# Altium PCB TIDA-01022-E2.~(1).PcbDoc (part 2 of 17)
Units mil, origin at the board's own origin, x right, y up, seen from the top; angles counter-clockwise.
Board outline 6929.13 x 11614.17 mil, 12 copper layers (L1_Top Layer, L2_GND, L3_GND, L4_Signal Layer 1, L5_GND, L6_PWR, L7_GND/PWR, L8_PWR, L9_GND/PWR, L10_Signal Layer 2, L11_GND, L12_Bottom Layer), stack 64.6 mil thick; 1711 components, 1001 nets, 5985 pads, 3200 vias.
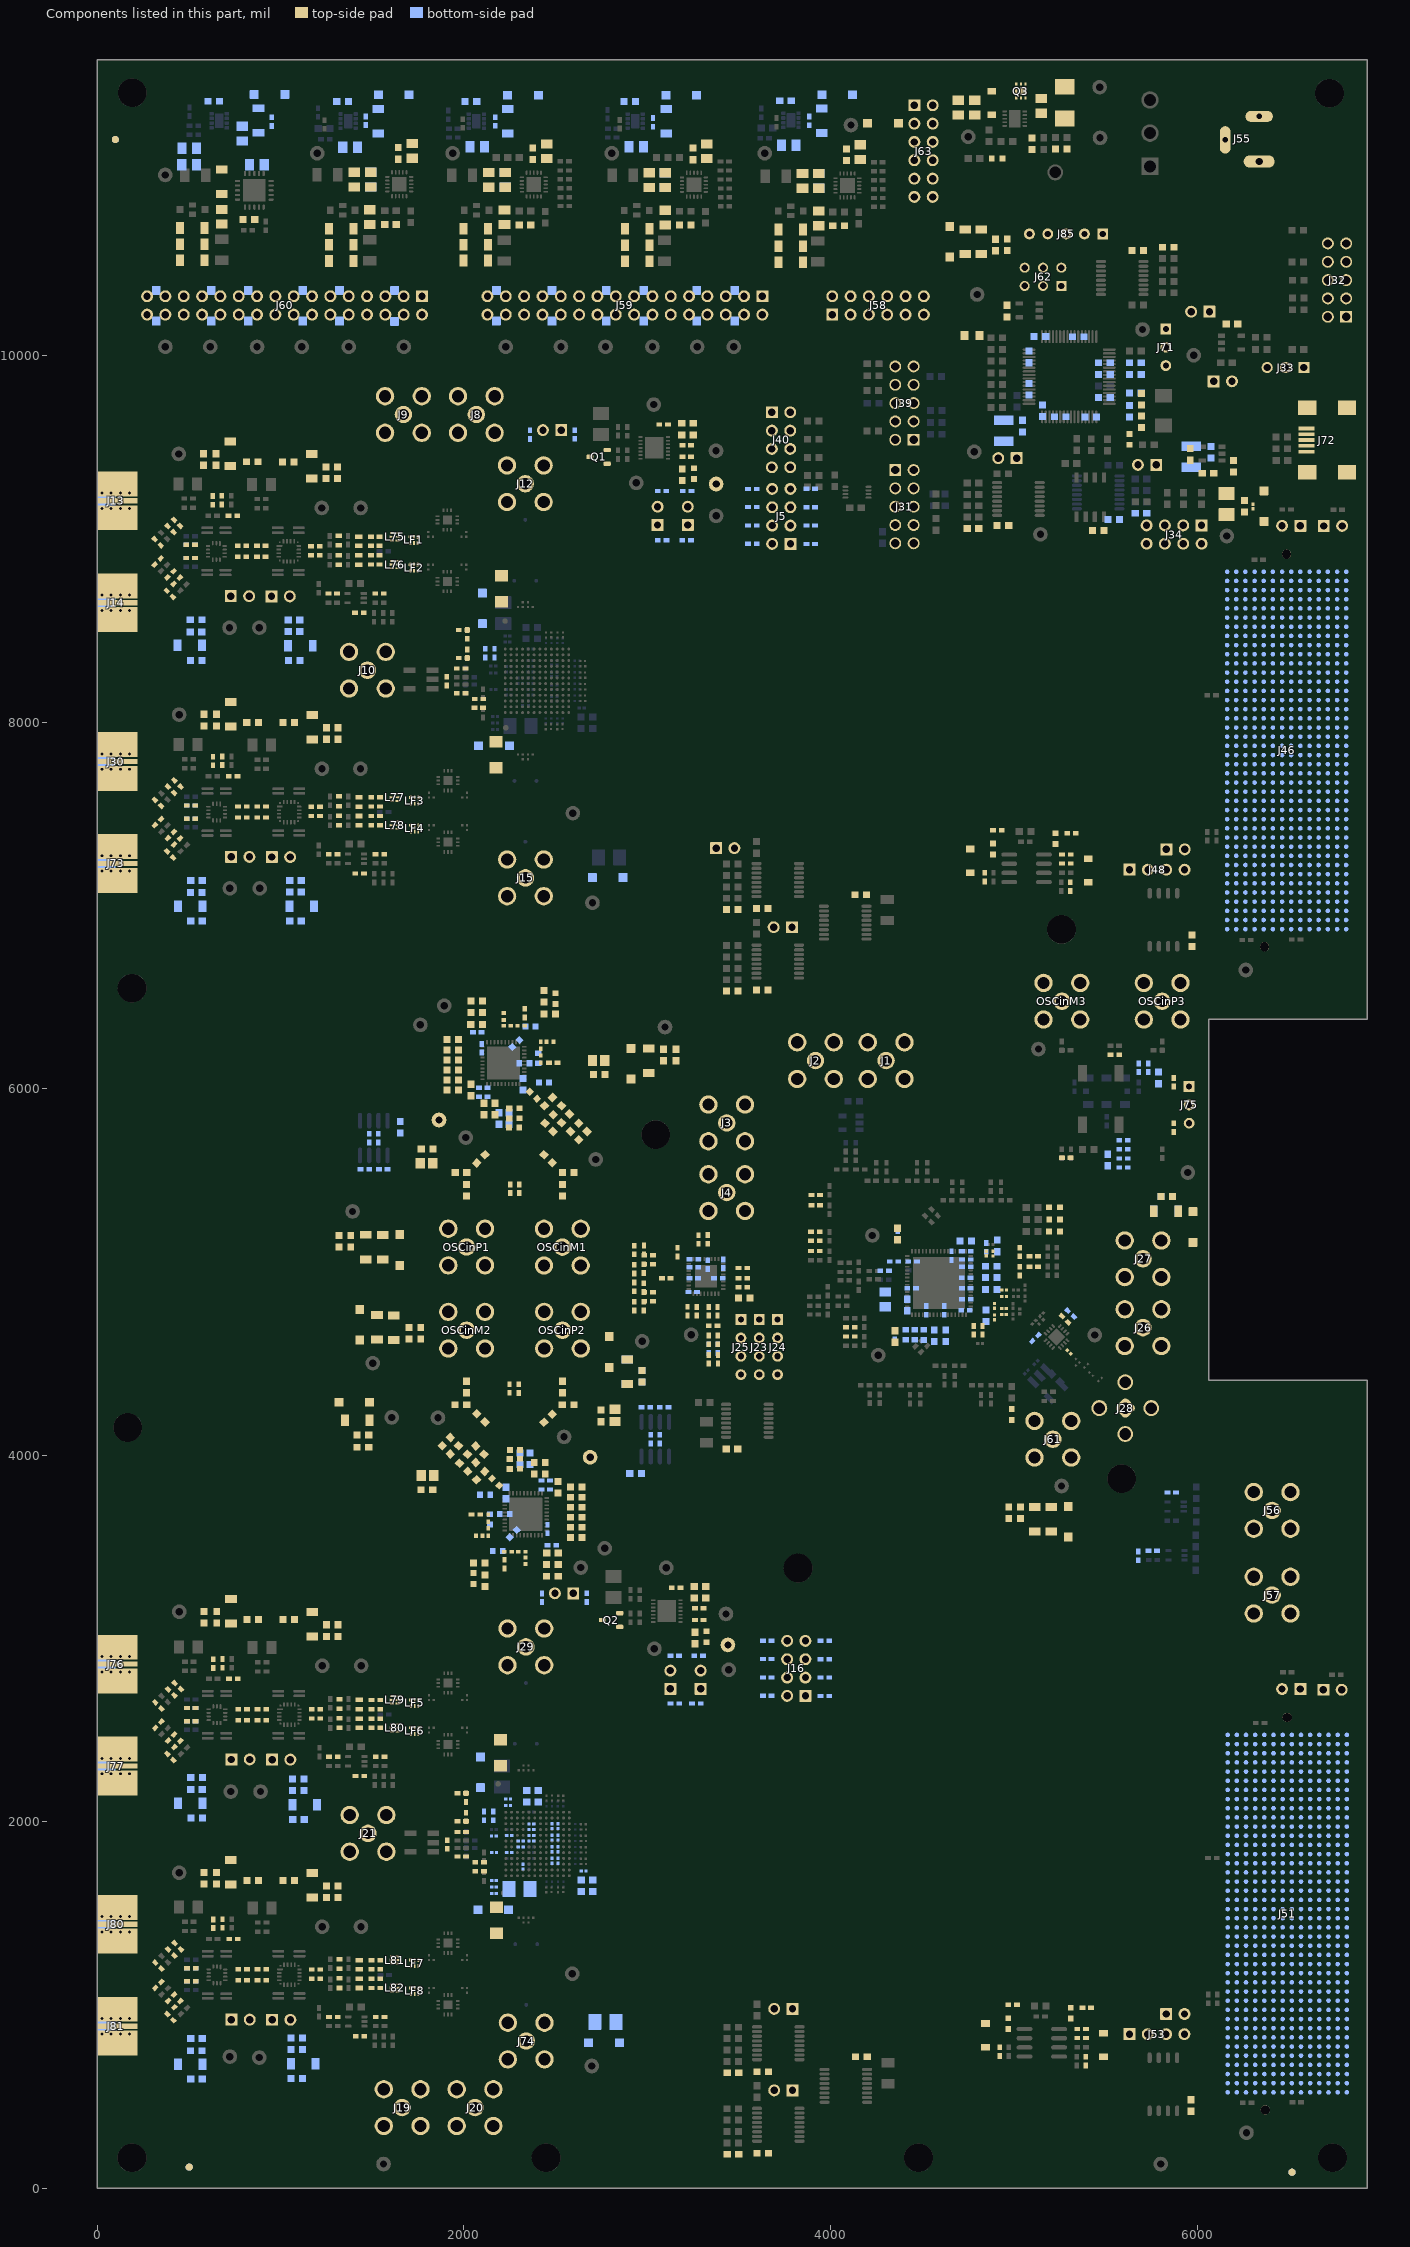
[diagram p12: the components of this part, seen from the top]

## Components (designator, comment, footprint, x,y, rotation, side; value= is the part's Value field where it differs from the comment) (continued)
C288 "GRM033C71A104KE14D" 0201#1 2367.24,1894.85 r0 bottom
C289 "GRM033C71A104KE14D" 0201#1 2367.24,1926.34 r0 bottom
C290 "GRM033C71A104KE14D" 0201#1 2367.24,1957.84 r0 bottom
C291 "GRM033C71A104KE14D" 0201#1 2367.24,1989.33 r0 bottom
C292 "C1608X5R1A105K080AC" 0603 2373.6,2108.56 r0 bottom
C293 "C1608X5R1A105K080AC" 0603 2373.6,2170.56 r0 bottom
C294 "293D106X0010B2TE3" 3528-21 2302.86,1632.5 r0 bottom
C295 "GRM033C71A104KE14D" 0201#1 2322.76,1755.87 r270 bottom
C296 "GRM033C71A104KE14D" 0201#1 2246.77,1926.34 r180 bottom
C297 "GRM033C71A104KE14D" 0201#1 2246.77,1831.85 r180 bottom
C298 "GRM033C71A104KE14D" 0201#1 2309.76,1894.85 r180 bottom
C299 "GRM033C71A104KE14D" 0201#1 2309.76,1863.35 r180 bottom
C300 "GRM033C71A104KE14D" 0201#1 2240.6,2124.56 r180 bottom
C301 "GRM033C71A104KE14D" 0201#1 2164.15,1831.8 r180 bottom
C302 "GRM033C71A104KE14D" 0201#1 2163.15,1921.8 r180 bottom
C303 "GRM033C71A104KE14D" 0201#1 2163.6,1680.56 r180 bottom
C304 "GRM033C71A104KE14D" 0201#1 2163.6,1644.56 r180 bottom
C305 "GRM033C71A104KE14D" 0201#1 2163.6,1609.56 r180 bottom
C306 "GRM033C71A104KE14D" 0201#1 2240.6,2089.56 r180 bottom
C307 "GRM033R60J104KE19D" 0201_033 5301,4563 r135 top
C308 "C1005X7R1E104M050BB" 0402#1 5310.3,4772.7 r135 bottom
C309 "293D106X0010B2TE3" 3528-21 2771.64,908.93 r0 bottom
C310 "GRM033C71A104KE14D" 0201#1 2511.73,1787.37 r90 bottom
C311 "GRM033C71A104KE14D" 0201#1 2480.24,1787.37 r90 bottom
C312 "GRM033C71A104KE14D" 0201#1 2480.24,1850.36 r90 bottom
C313 "GRM033C71A104KE14D" 0201#1 2511.73,1850.36 r90 bottom
C314 "GRM033C71A104KE14D" 0201#1 2652.77,1731.37 r0 bottom
C315 "GRM033C71A104KE14D" 0201#1 2480.24,1913.35 r270 bottom
C316 "GRM033C71A104KE14D" 0201#1 2511.73,1913.35 r270 bottom
C317 "GRM033C71A104KE14D" 0201#1 2480.24,1976.34 r270 bottom
C318 "GRM033C71A104KE14D" 0201#1 2511.73,1976.34 r270 bottom
C319 "C1608X5R1A105K080AC" 0603 2671.54,1682.24 r0 bottom
C320 "C1608X5R1A105K080AC" 0603 2671.54,1619.24 r0 bottom
C321 "C1005X7R1E104M050BB" 0402#1 2081.89,8126.19 r0 top
C322 "520L103KT16T" 0402_065 2331.07,6411.77 r270 top
C323 "C1608X7R1C105K080AC" 0603 2191.16,5836.72 r90 bottom
C324 "C1608X7R1C105K080AC" 0603L 2378.66,5963.82 r135 top
C325 "C1005X7R1E104M050BB" 0402#1 2080.51,8077.19 r0 top
C326 "C1608X7R1C105K080AC" 0603L 2329.56,6138.82 r180 bottom
C327 "0603YC104JAT2A" 0603L 2283.06,6246.02 r45 bottom
C328 "0603YC104JAT2A" 0603 1798.77,5670.52 r0 top
C329 "C0805C106K8PACTU" 0805 1795.77,5592.72 r0 top
C330 "C0805C106K8PACTU" 0805 2734.77,6153.85 r0 top
C331 "0603YC104JAT2A" 0603 2737.77,6078.05 r0 top
C332 "C1608X7R1C105K080AC" 0603 2069.28,6414.92 r0 top
C333 "C1608X7R1C105K080AC" 0603 1938.66,6047.12 r0 top
C334 "C1005X7R1E104M050BB" 0402#1 2085.22,1780.19 r0 top
C335 "GRM1885C1H122JA01D" 0603 1938.66,6156.42 r0 top
C336 "GRM1885C2A301JA01D" 0603 2603.66,5743.82 r315 top
C337 "GRM188R71H273KA61D" 0603 2553.66,5883.82 r315 top
C338 "520L103KT16T" 0402_065 2486.81,6141.72 r180 top
C339 "GRM1885C1H221JA01D" 0603 2460.85,5928.95 r225 top
C340 "C1608X7R1C105K080AC" 0603 2322,6024.32 r270 bottom
C341 "C1005X7R1E104M050BB" 0402#1 2085.22,1731.19 r0 top
C342 "C1608X5R1A106M080AC" 0603 1938.66,6102.02 r180 top
C343 "C1608X7R1C105K080AC" 0603 2038.16,5992.72 r90 top
C344 "C1608X5R1A106M080AC" 0603 1938.66,6267.52 r180 top
C345 "C1608X5R1A106M080AC" 0603 2168.66,5888.82 r270 top
C346 "C1608X5R1A106M080AC" 0603 2068.87,6350.82 r0 top
C347 "C1608X5R1A106M080AC" 0603 1938.66,6211.12 r0 top
C348 "0603YC104JAT2A" 0603L 2246.86,5864.22 r90 top
C349 "0603YC104JAT2A" 0603L 2302.04,5865.92 r90 top
C350 "0603YC104JAT2A" 0603 1651.97,5788.77 r90 bottom
C351 "GRM033R60J104KE19D" 0201_033 4894.89,4752 r90 top
C352 "520L103KT16T" 0402_065 2220.55,3406.2 r90 top
C353 "C1608X7R1C105K080AC" 0603 2360.46,3981.26 r270 bottom
C354 "C1608X7R1C105K080AC" 0603L 2172.96,3854.16 r315 top
C355 "GRM1555C1H471JA01D" 0402#1 3031.45,11271.2 r270 bottom
C356 "C1608X7R1C105K080AC" 0603L 2222.06,3679.16 r0 bottom
C357 "0603YC104JAT2A" 0603L 2268.56,3571.96 r225 bottom
C358 "0603YC104JAT2A" 0603 1797.65,3811.53 r180 top
C359 "C0805C106K8PACTU" 0805 1800.65,3889.33 r180 top
C360 "C0805C106K8PACTU" 0805 2824.18,4217.68 r270 top
C361 "0603YC104JAT2A" 0603 2748.38,4214.68 r270 top
C362 "C1608X7R1C105K080AC" 0603 2482.34,3403.06 r180 top
C363 "C1608X7R1C105K080AC" 0603 2612.96,3770.86 r180 top
C364 "GRM1555C1H471JA01D" 0402#1 2170.76,11276.39 r270 bottom
C365 "GRM1885C1H122JA01D" 0603 2612.96,3661.56 r180 top
C366 "GRM1885C2A301JA01D" 0603 1947.96,4074.16 r135 top
C367 "GRM188R71H273KA61D" 0603 1997.96,3934.16 r135 top
C368 "520L103KT16T" 0402_065 2064.8,3676.26 r0 top
C369 "GRM1885C1H221JA01D" 0603 2090.76,3889.03 r45 top
C370 "C1608X7R1C105K080AC" 0603 2229.61,3793.65 r90 bottom
C371 "GRM1555C1H471JA01D" 0402#1 3883.49,11279.9 r270 bottom
C372 "C1608X5R1A106M080AC" 0603 2612.96,3715.96 r0 top
C373 "C1608X7R1C105K080AC" 0603 2513.46,3825.26 r270 top
C374 "C1608X5R1A106M080AC" 0603 2612.96,3550.46 r0 top
C375 "C1608X5R1A106M080AC" 0603 2382.96,3929.16 r90 top
C376 "C1608X5R1A106M080AC" 0603 2482.75,3467.16 r180 top
C377 "C1608X5R1A106M080AC" 0603 2612.96,3606.86 r180 top
C378 "0603YC104JAT2A" 0603L 2304.76,3953.76 r270 top
C379 "0603YC104JAT2A" 0603L 2249.58,3952.06 r270 top
C380 "0603YC104JAT2A" 0603 2936.3,3899.45 r0 bottom
C381 "EMK107BBJ106MA-T" 0603 3529.5,4857.79 r180 top
C382 "C1005X7S1A105K050BC" 0402#1 3521.5,4916.29 r180 top
C383 "GRM155R71C104KA88D" 0402#1 3219,4786 r90 top
C384 "GRM155R71E103KA01D" 0402#1 3254.5,5025.29 r0 bottom
C385 "GRM155R71E103KA01D" 0402#1 3247.88,4890.67 r0 bottom
C386 "GRM155R71E103KA01D" 0402#1 3253.5,4965.29 r0 bottom
C387 "GRM155R71E103KA01D" 0402#1 3330.5,5040.29 r90 bottom
C388 "GRM155R71E103KA01D" 0402#1 3387.5,4965.29 r180 bottom
C389 "GRM155R71E103KA01D" 0402#1 3414.78,5044.67 r90 bottom
C390 "GRM155R71E103KA01D" 0402#1 3254.5,5069.79 r180 bottom
C391 "C1005X7R1E104M050BB" 0402#1 3335.5,4785.29 r90 top
C392 "C1005X7R1E104M050BB" 0402#1 3383.5,4785.29 r90 top
C393 "0201ZD392KAT2A" 0201#1 4886.47,5099.94 r90 top
C394 "C1005X7R1E104M050BB" 0402#1 3917.47,5169.44 r180 top
C395 "GRM0335C1E470JA01D" 0201_033 4849.35,5100.47 r90 top
C396 "C1005X7R1E104M050BB" 0402#1 3917.47,5114.44 r180 top
C397 "GRM033R60J104KE19D" 0201_033 4946.41,4866.77 r180 top
C398 "C1005X5R1A684K050BB" 0402#1 4828.97,4682.02 r90 top
C399 "C1005X7R1E104M050BB" 0402#1 4780.97,4682.02 r90 top
C400 "GRM033R60J104KE19D" 0201_033 4946.41,4900.77 r180 top
C401 "C1005X7R1E104M050BB" 0402#1 4108.01,4698.08 r180 top
C402 "C1005X7R1E104M050BB" 0402#1 4108.01,4648.08 r180 top
C403 "GRM033R60J104KE19D" 0201_033 4945.97,4769.02 r180 top
C404 "GRM033R60J104KE19D" 0201_033 4945.97,4801.02 r180 top
C405 "GRM033R60J104KE19D" 0201_033 4894.89,4815 r270 top
C406 "C1005X7R1E104M050BB" 0402#1 5031.66,5004.8 r90 top
C407 "C1005X7R1E104M050BB" 0402#1 5108.66,5028.8 r0 top
C408 "C1005X7R1E104M050BB" 0402#1 5108.66,5085.8 r0 top
C409 "C0402C120J3GACAUTO" 0402#1 5031.66,5108.8 r270 top
C410 "C1005X7R1E104M050BB" 0402#1 5285.7,5622.27 r180 top
C411 "C1005X5R0J475M050BC" 0402#1 5733.97,6113.84 r270 bottom
C412 "GRM155R71E103KA01D" 0402#1 5680.97,6113.84 r270 bottom
C413 "C1005X7R1E104M050BB" 0402#1 3919.28,5419.5 r180 top
C414 "GRM1555C1H100JA01D" 0402#1 5598.08,5669.02 r180 bottom
C415 "C1005X7R1E104M050BB" 0402#1 3919.28,5364.5 r180 top
C416 "GRM155R71E222KA01D" 0402#1 5598.08,5619.02 r180 bottom
C417 "C1005X7R1E104M050BB" 0402#1 5550.66,6185.09 r0 top
C418 "04025A101FAT2A" 0402#1 5598.08,5719.02 r180 bottom
C419 "C1005X7R1E104M050BB" 0402#1 5598.08,5570.02 r180 bottom
C420 "C1005X7S1A105K050BC" 0402#1 4441.66,4910.2 r0 bottom
C421 "GRM155R71C104KA88D" 0402#1 4740.87,4851.14 r180 bottom
C422 "GRM155R71E103KA01D" 0402#1 4735.97,4791.02 r180 bottom
C423 "C1005X7R1E104M050BB" 0402#1 4447.89,5057 r180 bottom
C424 "C1005X7R1E104M050BB" 0402#1 4294.47,5006.94 r0 bottom
C425 "C0603C330J5GACTU" 0603L 4507.97,4656.95 r90 bottom
C426 "C0603C330J5GACTU" 0603L 4458.97,4657.46 r90 bottom
C427 "C0603C330J5GACTU" 0603L 4409.97,4657.02 r90 bottom
C428 "C1005X7S1A105K050BC" 0402#1 4620.79,4790.12 r90 bottom
C429 "C1005X7S1A105K050BC" 0402#1 4522.36,4790.12 r90 bottom
C430 "C1005X7S1A105K050BC" 0402#1 4350.97,4655.89 r270 bottom
C431 "C0603C104J3RACTU" 0603 4418.03,4819.65 r270 bottom
C432 "C0805C106K8PACTU" 0805_HV 4298.97,4850.02 r270 bottom
C433 "C1005X7S1A105K050BC" 0402#1 4848.97,5134.02 r90 bottom
C434 "GRM155R71C104KA88D" 0402#1 4741.35,5112.02 r180 bottom
C435 "GRM155R71E103KA01D" 0402#1 4740.87,5067.68 r180 bottom
C436 "C1005X7R1E104M050BB" 0402#1 4740.87,5028.31 r0 bottom
C437 "C1005X7R1E104M050BB" 0402#1 4739.47,4967.94 r0 bottom
C438 "C1005X7R1E104M050BB" 0402#1 4740.47,4910.94 r0 bottom
C439 "C1005X7S1A105K050BC" 0402#1 4365.97,5199.14 r90 bottom
C440 "C1005X7S1A105K050BC" 0402#1 4660.16,5089.33 r270 bottom
C441 "C0603C104J3RACTU" 0603 5675.72,10572.95 r0 top
C442 "C0603C104J3RACTU" 0603 5841.84,10590.12 r180 top
C443 "C0603C104J3RACTU" 0603 4777.32,9056.2 r0 top
C444 "C0603C104J3RACTU" 0603 4940.2,9072.76 r180 top
C445 "C0603C104J3RACTU" 0603 6190.08,10170.75 r0 top
C446 "C1005X7S1A105K050BC" 0402#1 5117,4639 r225 bottom
C447 "C0603C104J3RACTU" 0603 5544.82,9105 r0 bottom
C448 "C0603C104J3RACTU" 0603 5693.31,9139.2 r180 bottom
C449 "C0603C104J3RACTU" 0603 3627.07,6537.73 r180 top
C450 "C0603C104J3RACTU" 0603 3463.97,6532.22 r0 top
C451 "C0603C104J3RACTU" 0603 3630.4,191.73 r180 top
C452 "C0603C104J3RACTU" 0603 3467.31,186.22 r0 top
C453 "C0603C104J3RACTU" 0603 3626.82,6982.68 r180 top
C454 "C0603C104J3RACTU" 0603 3463.97,6976.93 r0 top
C455 "C0603C104J3RACTU" 0603 3629.91,636.44 r180 top
C456 "C0603C104J3RACTU" 0603 3467.31,630.93 r0 top
C457 "GRM188R61A106ME69D" 0603 5662.88,9794.97 r0 bottom
C458 "C0603C104J3RACTU" 0603 5493.88,9770.97 r0 bottom
C459 "C0603C104J3RACTU" 0603 5418.88,9663.97 r0 bottom
C460 "C0603C104J3RACTU" 0603 5493.88,9959.97 r0 bottom
C461 "C0603C104J3RACTU" 0603 5083.38,9992.24 r270 bottom
C462 "C0603C104J3RACTU" 0603 5141.88,10102.97 r0 bottom
C463 "C0603C104J3RACTU" 0603 5083.38,9815.07 r90 bottom
C464 "C0603C104J3RACTU" 0603 5351.1,10102.47 r0 bottom
C465 "C0603C104J3RACTU" 0603 5252.67,9665.47 r0 bottom
C466 "GRM188R61A106ME69D" 0603 5662.88,9895.97 r0 bottom
C467 "C0603C104J3RACTU" 0603 5493.88,9895.97 r0 bottom
C468 "C0603C104J3RACTU" 0603 4962.88,10241.97 r270 top
C469 "C0603C104J3RACTU" 0603 5156.87,9697.98 r270 bottom
C470 "C1608X7R1C105K080AC" 0603 6059.02,9357.58 r0 top
C471 "GRM32ER61A107ME20L" 1210_270 5967,9448 r270 bottom
C472 "C0603C104J3RACTU" 0603 6075,9472 r90 bottom
C473 "C1608X7R1C105K080AC" 0603 6198,9395 r270 top
C474 "GRM32ER61A107ME20L" 1210_270 4944.87,9588.47 r270 bottom
C475 "C1608X5R1A105K080AC" 0603 5972.09,6807.18 r90 top
C476 "C1608X5R1A105K080AC" 0603 5966.26,452.43 r90 top
C477 "08053D105KAT2A" 0805_HV 4785.82,11352.8 r90 top
C478 "08053D105KAT2A" 0805_HV 4695.82,11352.8 r90 top
C479 "08053D105KAT2A" 0805_HV 5149.32,11361.73 r90 top
C480 "06031C102MAT2A" 0603 5258.82,11125.8 r0 top
C481 "06031C102MAT2A" 0603 5099.82,11154.8 r270 top
C482 "293D106X0010B2TE3" 3528-21 6161,9189 r90 top
C483 "GRM033C71A104KE14D" 0201#1 6304,9176 r90 top
C484 "C1608X5R1A105K080AC" 0603 6258,9177 r90 top
C485 "CGA3E2X7R1H104K080AA" 0603 2970.44,4430.98 r270 top
C486 "C3216X5R1E336M160AC" 1206_180 2890,4456 r270 top
C487 "C3216X7R1E106M160AE" 1206_190 2890,4456 r90 bottom
C488 "GCM188R71H103KA37D" 0603 2970.44,4430.98 r270 bottom
C489 "C0603C104J3RACTU" 0603 3462.18,4033.15 r180 top
C490 "GRM155R71C104JA88D" 0402#1 434.91,9086.79 r135 top
C491 "GRM155R71C104JA88D" 0402#1 432.91,8770.79 r45 top
C492 "GRM155R71E103KA01D" 0402#1 394.91,8699.79 r315 top
C493 "GRM155R71C104JA88D" 0402#1 436.71,7664.66 r135 top
C494 "C3216X7R1E106M160AE" 1206_190 3102.66,11277.33 r270 bottom
C495 "JMK212BJ226MG-T" 0805_HV 2939.35,11139.04 r0 bottom
C496 "C3216X7R1E106M160AE" 1206_190 2944.52,10691.04 r0 top
C497 "C3216X7R1E106M160AE" 1206_190 2945.52,10602.04 r0 top
C498 "C3216X7R1E106M160AE" 1206_190 2945.52,10513.04 r0 top
C499 "GRM155R71C104JA88D" 0402#1 434.71,7348.66 r45 top
C500 "GRM155R71E103KA01D" 0402#1 396.71,7277.66 r315 top
C501 "GRM1885C1H332JA01D" 0603 2904.66,11385.33 r180 bottom
C502 "GRM155R71C104JA88D" 0402#1 438.23,2740.42 r135 top
C503 "GRM155R71C104JA88D" 0402#1 436.23,2424.42 r45 top
C504 "GRM155R71E103KA01D" 0402#1 398.23,2353.42 r315 top
C505 "GRM155R71C104JA88D" 0402#1 438.3,1321.09 r135 top
C506 "GRM155R71C104JA88D" 0402#1 436.3,1005.09 r45 top
C507 "GRM155R71E103KA01D" 0402#1 398.3,934.09 r315 top
C508 "GRM155R71C104KA88D" 0402#1 5861.47,3797.1 r0 bottom
C509 "GRM1555C1H471JA01D" 0402#1 1463.76,11280.63 r270 bottom
C510 "GRM1555C1H471JA01D" 0402#1 952,11275.92 r270 bottom
C511 "GRM155R71C104KA88D" 0402#1 5757.86,3478.92 r180 bottom
C512 "GRM155R71E103KA01D" 0402#1 5279.3,4741.7 r135 top
C516 "GRM21BR61C106KE15L" 0805_HV 3097.92,10956.68 r270 top
C517 "GRM21BR61C106KE15L" 0805_HV 3097.92,10956.68 r270 bottom
C518 "GRM219R60G476ME44D" 0805_HV 3009.92,10956.68 r270 top
C519 "GRM219R60G476ME44D" 0805_HV 3097.92,10752.64 r90 top
C522 "GRM188R71H103KA01D" 0603 3206.92,10711.68 r0 top
C523 "GRM21BR61C106KE15L" 0805_HV 3324.92,11113.68 r90 top
C524 "GRM188R71H103KA01D" 0603 3248.92,11099.68 r90 top
C537 "C3216X7R1E106M160AE" 1206_190 2238.76,11277.39 r270 bottom
C538 "JMK212BJ226MG-T" 0805_HV 2072.01,11138.99 r0 bottom
C539 "C3216X7R1E106M160AE" 1206_190 2064.07,10518 r0 top
C540 "C3216X7R1E106M160AE" 1206_190 2063.07,10605 r0 top
C541 "C3216X7R1E106M160AE" 1206_190 2064.07,10692 r0 top
C544 "GRM1885C1H332JA01D" 0603 2037.66,11385.28 r180 bottom
C587 "GRM21BR61C106KE15L" 0805_HV 2136.09,10957.54 r270 top
C588 "GRM21BR61C106KE15L" 0805_HV 2224.09,10957.54 r270 bottom
C589 "GRM219R60G476ME44D" 0805_HV 2224.09,10957.54 r270 top
C590 "GRM219R60G476ME44D" 0805_HV 2221,10754 r90 top
C593 "GRM188R71H103KA01D" 0603 2333.09,10712.54 r0 top
C594 "GRM21BR61C106KE15L" 0805_HV 2451.09,11114.54 r90 top
C595 "GRM188R71H103KA01D" 0603 2375.09,11100.54 r90 top
C596 "CGA3E2X7R1H104K080AA" 0603 1382.17,5166.8 r270 top
C597 "C3216X5R1E336M160AC" 1206_180 1556.17,5134.8 r270 top
C598 "C3216X7R1E106M160AE" 1206_190 1465.17,5135.8 r90 top
C599 "GCM188R71H103KA37D" 0603 1317.17,5166.8 r270 top
C600 "C3216X7R1E106M160AE" 1206_190 3951.67,11281.46 r270 bottom
C601 "JMK212BJ226MG-T" 0805_HV 3771.63,11146.77 r0 bottom
C602 "C3216X7R1E106M160AE" 1206_190 3781.74,10687.14 r0 top
C603 "C3216X7R1E106M160AE" 1206_190 3781.9,10596.67 r0 top
C604 "C3216X7R1E106M160AE" 1206_190 3781.9,10509.36 r0 top
C605 "CGA3E2X7R1H104K080AA" 0603 3088.8,6183.28 r270 top
C606 "C3216X7R1E106M160AE" 1206_190 3007.8,6152.28 r90 top
C607 "GCM188R71H103KA37D" 0603 3155.8,6183.28 r270 top
C608 "GRM1885C1H332JA01D" 0603 3753.67,11389.46 r180 bottom
C609 "CGA3E2X7R1H104K080AA" 0603 1699.34,4665.4 r90 top
C610 "C3216X5R1E336M160AC" 1206_180 1616.34,4696.4 r90 top
C611 "C3216X7R1E106M160AE" 1206_190 1525.34,4697.4 r270 top
C612 "GCM188R71H103KA37D" 0603 1764.34,4665.4 r90 top
C613 "GRM21BR61C106KE15L" 0805_HV 3846.9,10952.67 r270 top
C614 "GRM21BR61C106KE15L" 0805_HV 3934.9,10952.67 r270 top
C615 "GRM219R60G476ME44D" 0805_HV 3934.9,10952.67 r270 bottom
C616 "GRM219R60G476ME44D" 0805_HV 3934.9,10747.67 r90 top
C619 "GRM188R71H103KA01D" 0603 4043.9,10707.67 r0 top
C620 "GRM21BR61C106KE15L" 0805_HV 4161.9,11109.67 r90 top
C621 "GRM188R71H103KA01D" 0603 4085.9,11095.67 r90 top
C622 "CGA3E2X7R1H104K080AA" 0603 1448.43,4110.16 r180 top
C623 "C3216X7R1E106M160AE" 1206_190 1417.43,4191.16 r0 top
C624 "GCM188R71H103KA37D" 0603 1448.43,4043.16 r180 top
C625 "CGA3E2X7R1H104K080AA" 0603 4972.23,3686.01 r270 top
C626 "C3216X5R1E336M160AC" 1206_180 5113.35,3651.01 r270 top
C627 "C3216X7R1E106M160AE" 1206_190 5203.35,3651.01 r90 top
C628 "GCM188R71H103KA37D" 0603 5036.23,3686.01 r270 top
C629 "CGA3E2X7R1H104K080AA" 0603 5834.43,5412.23 r180 top
C630 "C3216X5R1E336M160AC" 1206_180 5830,5330 r180 top
C631 "C3216X7R1E106M160AE" 1206_190 5830,5330 r0 bottom
C632 "GCM188R71H103KA37D" 0603 5834.43,5412.23 r180 bottom
C633 "CGA3E2X7R1H104K080AA" 0603 4900.47,10602.82 r90 top
C634 "C3216X5R1E336M160AC" 1206_180 4735.85,10620.25 r90 top
C635 "C3216X7R1E106M160AE" 1206_190 4820.84,10620.25 r270 top
C636 "GCM188R71H103KA37D" 0603 4963.47,10603.82 r90 top
C637 "CGA3E2X7R1H104K080AA" 0603 1247.54,9359.71 r90 top
C638 "CGA3E2X7R1H104K080AA" 0603 1250.44,3043.29 r90 top
C639 "C3216X7R1E106M160AE" 1206_190 1169.54,9394.71 r270 top
C640 "GCM188R71H103KA37D" 0603 1310.54,9359.71 r90 top
C641 "C3216X7R1E106M160AE" 1206_190 1172.44,3078.29 r270 top
C642 "GCM188R71H103KA37D" 0603 1313.44,3043.29 r90 top
C643 "C3216X7R1E106M160AE" 1206_190 1531.76,11277.63 r270 bottom
C644 "C3216X7R1E106M160AE" 1206_190 1330.07,10691.4 r0 top
C645 "C3216X7R1E106M160AE" 1206_190 1331.07,10603.4 r0 top
C646 "C3216X7R1E106M160AE" 1206_190 1331.07,10515.4 r0 top
C647 "JMK212BJ226MG-T" 0805_HV 1378.66,11134.81 r0 bottom
C648 "CGA3E2X7R1H104K080AA" 0603 1249.34,7937.59 r90 top
C649 "C3216X7R1E106M160AE" 1206_190 1171.51,1653.95 r270 top
C650 "CGA3E2X7R1H104K080AA" 0603 1249.51,1618.95 r90 top
C651 "C3216X7R1E106M160AE" 1206_190 1171.34,7972.59 r270 top
C652 "GCM188R71H103KA37D" 0603 1312.34,7937.59 r90 top
C653 "GCM188R71H103KA37D" 0603 1312.51,1618.95 r90 top
C654 "GRM1885C1H332JA01D" 0603 1337.87,11385.5 r180 bottom
C655 "GRM21BR61C106KE15L" 0805_HV 1402.22,10959.4 r270 top
C656 "GRM21BR61C106KE15L" 0805_HV 1490.22,10959.4 r270 top
C657 "GRM219R60G476ME44D" 0805_HV 1490.22,10959.4 r270 bottom
C658 "CGA3E2X7R1H104K080AA" 0603 647.91,9432.79 r90 top
C659 "CGA3E2X7R1H104K080AA" 0603 650.81,3116.36 r90 top
C660 "GRM219R60G476ME44D" 0805_HV 1486,10755 r90 top
C663 "C3216X7R1E106M160AE" 1206_190 725.91,9464.79 r270 top
C664 "GCM188R71H103KA37D" 0603 578.91,9432.79 r90 top
C665 "C3216X7R1E106M160AE" 1206_190 728.81,3148.36 r270 top
C666 "GCM188R71H103KA37D" 0603 581.81,3116.36 r90 top
C667 "GRM188R71H103KA01D" 0603 1599.22,10714.4 r0 top
C668 "GRM21BR61C106KE15L" 0805_HV 1717.22,11116.4 r90 top
C669 "GRM188R71H103KA01D" 0603 1641.22,11102.4 r90 top
C670 "CGA3E2X7R1H104K080AA" 0603 649.71,8010.66 r90 top
C671 "CGA3E2X7R1H104K080AA" 0603 649.88,1692.02 r90 top
C672 "C3216X7R1E106M160AE" 1206_190 727.71,8042.66 r270 top
C673 "GCM188R71H103KA37D" 0603 580.71,8010.66 r90 top
C674 "C3216X7R1E106M160AE" 1206_190 727.88,1724.02 r270 top
C675 "GCM188R71H103KA37D" 0603 580.88,1692.02 r90 top
C688 "CGA3E2X7R1H104K080AA" 0603 1072.79,8494.35 r0 bottom
C689 "CGA3E2X7R1H104K080AA" 0603 537.91,8491.99 r180 bottom
C690 "C3216X7R1E106M160AE" 1206_190 879,11281.92 r270 bottom
C691 "C3216X7R1E106M160AE" 1206_190 1107.79,8416.35 r180 bottom
C692 "GCM188R71H103KA37D" 0603 1072.79,8557.35 r0 bottom
C693 "C3216X7R1E106M160AE" 1206_190 503.91,8417.99 r0 bottom
C694 "GCM188R71H103KA37D" 0603 538.41,8557.99 r180 bottom
C695 "JMK212BJ226MG-T" 0805_HV 789.8,11210.36 r90 bottom
C696 "JMK212BJ226MG-T" 0805_HV 500,11040.92 r180 bottom
C697 "JMK212BJ226MG-T" 0805_HV 501,11129.92 r180 bottom
C698 "GRM1885C1H332JA01D" 0603 634.55,11387.32 r180 bottom
C699 "CGA3E2X7R1H104K080AA" 0603 1080.66,7072.56 r0 bottom
C700 "CGA3E2X7R1H104K080AA" 0603 539.71,7069.86 r180 bottom
C701 "C3216X7R1E106M160AE" 1206_190 1115.66,6994.56 r180 bottom
C702 "GCM188R71H103KA37D" 0603 1080.66,7135.56 r0 bottom
C703 "C3216X7R1E106M160AE" 1206_190 505.71,6995.86 r0 bottom
C704 "GCM188R71H103KA37D" 0603 540.2,7135.86 r180 bottom
C705 "C3216X7R1E106M160AE" 1206_190 518.07,10695.4 r0 top
C706 "C3216X7R1E106M160AE" 1206_190 517.96,10607.1 r0 top
C707 "C3216X7R1E106M160AE" 1206_190 518.07,10519.4 r0 top
C708 "CGA3E2X7R1H104K080AA" 0603 1096.36,2171.46 r0 bottom
C709 "CGA3E2X7R1H104K080AA" 0603 540.81,2175.56 r180 bottom
C710 "C3216X7R1E106M160AE" 1206_190 1131.36,2093.46 r180 bottom
C711 "GCM188R71H103KA37D" 0603 1096.36,2234.46 r0 bottom
C712 "C3216X7R1E106M160AE" 1206_190 506.81,2101.56 r0 bottom
C713 "GCM188R71H103KA37D" 0603 541.3,2241.56 r180 bottom
C714 "GRM219R60G476ME44D" 0805_HV 679,10757 r90 top
C715 "C3216X7R1E106M160AE" 1206_190 679.62,10947.81 r90 top
C716 "GRM188R71H103KA01D" 0603 826.5,10742.57 r0 top
C717 "CGA3E2X7R1H104K080AA" 0603 1087.02,757.38 r0 bottom
C718 "CGA3E2X7R1H104K080AA" 0603 539.88,751.22 r180 bottom
C719 "C3216X7R1E106M160AE" 1206_190 1122.02,679.38 r180 bottom
C720 "GCM188R71H103KA37D" 0603 1087.02,820.38 r0 bottom
C721 "C3216X7R1E106M160AE" 1206_190 505.88,677.22 r0 bottom
C722 "GCM188R71H103KA37D" 0603 540.38,817.22 r180 bottom
C723 "08053D105KAT2A" 0805_HV 870.42,11041.57 r0 bottom
C736 "GRM188R61A106ME69D" 0603 5047.87,9614.47 r270 bottom
C737 "C0603C104J3RACTU" 0603 4164.82,7057.51 r0 top
C738 "C0603C104J3RACTU" 0603 5460.88,9044.97 r0 top
C739 "GRM1885C2A160JA01D" 0603 5695.88,9638.97 r270 top
C740 "GRM1885C2A160JA01D" 0603 5695.88,9760.97 r90 top
C741 "C0603C104J3RACTU" 0603 4168.15,718.52 r0 top
CALSAT1 "5002" Keystone5002 3375.44,9298.69 r180 top
CALSAT2 "5002" Keystone5002 3440,2965 r180 top
CE_TP1 "5002" Keystone5002 1863.66,5828.82 r135 top
CE_TP2 "5002" Keystone5002 2687.96,3989.16 r45 top
D1 "LTST-C190KFKT" LED_LTST-C190 4886.21,7307.18 r90 top
D2 "1N4148W-7-F" SOD-123 4762.2,7243.18 r90 top
D3 "LTST-C190KFKT" LED_LTST-C190 5227.21,7364.18 r90 top
D4 "1N4148W-7-F" SOD-123 5406.21,7190.18 r90 top
D5 "LTST-C190GKT" LED_LTST-C190 3255.1,9355.55 r270 top
D6 "LTST-C190KFKT" LED_LTST-C190 4969.3,899.25 r90 top
D7 "1N4148W-7-F" SOD-123 4845.3,835.26 r90 top
D8 "LTST-C190KFKT" LED_LTST-C190 5310.3,956.25 r90 top
D9 "1N4148W-7-F" SOD-123 5489.3,782.26 r90 top
D10 "LTST-C190GKT" LED_LTST-C190 3323.43,3009.79 r270 top
D11 "LTST-C191TGKT" LTST-C191_Green 2499.81,6490.72 r90 top
D12 "LTST-C191TGKT" LTST-C191_Green 2051.8,3327.26 r270 top
D13 "LTST-C191TGKT" LTST-C191_Green 5221.49,5353.39 r0 top
D14 "LTST-C191TGKT" LTST-C191_Green 5222.03,5286.39 r0 top
D15 "LTST-C191TGKT" LTST-C191_Green 4988.39,4221.97 r270 top
D16 "LTST-C191TGKT" LTST-C191_Green 5221.47,5220.14 r0 top
D17 "LTST-C191TGKT" LTST-C191_Green 5630.88,9541.97 r270 top
D18 "150080GS75000" WL-SMCW_Green_0805 4772,10109 r0 top
D19 "SMBJ15CA" SMB-Bi 5277.82,11379.8 r270 top
D20 "MBR130T1G" SOD-123 4878.82,11376.8 r90 top
D21 "LTST-C191TGKT" LTST-C191_Green 4908.82,11074.8 r0 top
FID1 "Fiducial" Fiducial10-20 98,11178 r90 top
FID2 "Fiducial" Fiducial10-20 501,116 r90 top
FID3 "Fiducial" Fiducial10-20 6517.09,88.18 r90 top
FID4 "Fiducial" Fiducial10-20 98,11178 r90 bottom
FID5 "Fiducial" Fiducial10-20 501,116 r90 bottom
FID6 "Fiducial" Fiducial10-20 6517.09,88.18 r90 bottom
J1 "142-0701-201" Johnson_142-0701-20x 4302.89,6153 r0 top
J2 "142-0701-201" Johnson_142-0701-20x 3917.7,6153.02 r0 top
J3 "142-0701-201" Johnson_142-0701-20x 3433.47,5813.02 r0 top
J4 "142-0701-201" Johnson_142-0701-20x 3433.47,5433.02 r0 top
J5 "TSW-104-07-G-D" TSW-104-07-G-D 3731.08,9121.88 r90 top
J6 "TSW-102-07-G-S" TSW-102-07-G-S 3056.08,9124.99 r90 top
J7 "TSW-102-07-G-S" TSW-102-07-G-S 3221.08,9124.99 r90 top
J8 "142-0701-201" Johnson_142-0701-20x 2067.22,9677.9 r90 top
J9 "142-0701-201" Johnson_142-0701-20x 1669.62,9677.9 r90 top
J10 "142-0701-201" Johnson_142-0701-20x 1473.08,8282.9 r270 top
J11 "TSW-102-07-G-S" TSW-102-07-G-S 2480.82,9592.56 r180 top
J12 "142-0701-201" Johnson_142-0701-20x 2334.48,9300.21 r270 top
J13 "142-0771-831" JOHNSON_142-0771-831 0,9206.79 r90 top
J14 "142-0771-831" JOHNSON_142-0771-831 0,8650.69 r90 top
J15 "142-0701-201" Johnson_142-0701-20x 2335.24,7149.98 r90 top
J16 "TSW-104-07-G-D" TSW-104-07-G-D 3812.72,2836.99 r90 top
J17 "TSW-102-07-G-S" TSW-102-07-G-S 3126.01,2775.21 r90 top
J18 "TSW-102-07-G-S" TSW-102-07-G-S 3291.01,2775.21 r90 top
J19 "142-0701-201" Johnson_142-0701-20x 1662.64,440.91 r270 top
J20 "142-0701-201" Johnson_142-0701-20x 2060.24,440.91 r270 top
J21 "142-0701-201" Johnson_142-0701-20x 1476.41,1936.9 r270 top
J22 "TSW-102-07-G-S" TSW-102-07-G-S 2546.15,3246.57 r180 top
J23 "800-10-004-10-001000" Mill-Max_800-10-004-10-001000 3610.74,4589.66 r270 top
J24 "800-10-004-10-001000" Mill-Max_800-10-004-10-001000 3710.74,4589.66 r270 top
J25 "800-10-004-10-001000" Mill-Max_800-10-004-10-001000 3510.74,4589.66 r270 top
J26 "142-0701-201" Johnson_142-0701-20x 5704.79,4696.07 r180 top
J27 "142-0701-201" Johnson_142-0701-20x 5704.79,5071.8 r180 top
J28 "32K101-400L5" Rosenberger_32K101-400L5 5607.84,4257.16 r315 top
J29 "142-0701-201" Johnson_142-0701-20x 2337.48,2954.59 r0 top
J30 "142-0771-831" JOHNSON_142-0771-831 0,7784.66 r90 top
J31 "61301021121" WURTH_61301021121 4403,9175 r270 top
J32 "61301021121" WURTH_61301021121 6763,10411 r90 top
J33 "HTSW-103-09-G-S" Samtec_HTSW-103-09-x-S 6482,9934 r180 top
J34 "TSW-104-07-G-D" TSW-104-07-G-D 5874,9023 r180 top
J35 "TSW-102-07-G-S" TSW-102-07-G-S 6017,10239 r180 top
J36 "TSW-102-07-G-S" TSW-102-07-G-S 4964.82,9440 r180 top
J37 "TSW-102-07-G-S" TSW-102-07-G-S 6140,9859 r0 top
J38 "TSW-102-07-G-S" TSW-102-07-G-S 5727,9403 r180 top
J39 "61301021121" WURTH_61301021121 4403,9740 r90 top
J40 "TSW-104-07-G-D" TSW-104-07-G-D 3729.92,9540 r270 top
J41 "TSW-102-07-G-S" TSW-102-07-G-S 3739.07,6880.73 r180 top
J42 "TSW-102-07-G-S" TSW-102-07-G-S 3742.4,534.73 r180 top
J43 "TSW-102-07-G-S" TSW-102-07-G-S 3425.43,7312.26 r0 top
J44 "TSW-102-07-G-S" TSW-102-07-G-S 3742.4,979.44 r180 top
J45 "TSW-102-07-G-S" TSW-102-07-G-S 6513.11,9070.71 r180 top
J46 "ASP-184330-01" ASP-184330-01#1 6488.11,7845.01 r90 bottom
J47 "TSW-102-07-G-S" TSW-102-07-G-S 5882.09,7305.18 r0 top
J48 "5-146278-4" TE_5-146278-4 5781.21,7194.68 r0 top
J49 "TSW-102-07-G-S" TSW-102-07-G-S 6740.81,9070.01 r0 top
J50 "TSW-102-07-G-S" TSW-102-07-G-S 6513.13,2724.51 r180 top
J51 "ASP-184330-01" ASP-184330-01#2 6491.44,1499.01 r90 bottom
J52 "TSW-102-07-G-S" TSW-102-07-G-S 5880.85,951.48 r0 top
J53 "5-146278-4" TE_5-146278-4 5780.4,841.39 r0 top
J54 "TSW-102-07-G-S" TSW-102-07-G-S 6738.13,2720.51 r0 top
J55 "RAPC722X" CONN_RAPC722X 6338,11599.07 r90 top
J56 "142-0701-201" Johnson_142-0701-20x 6408.9,3698.82 r270 top
J57 "142-0701-201" Johnson_142-0701-20x 6408.9,3236.82 r270 top
J58 "PEC06DAAN" CONN_PEC06DAAN 4259,10273 r0 top
J59 "TSW-116-07-G-D" TSW-116-07-G-D 2878,10273 r180 top
J60 "TSW-116-07-G-D" TSW-116-07-G-D 1021,10273 r180 top
J61 "142-0701-201" Johnson_142-0701-20x 5212.88,4087.24 r0 top
J62 "802-10-006-10-001000" Mill-Max_802-10-006-10-001000 5159,10429 r180 top
J63 "PEC06DAAN" CONN_PEC06DAAN 4507,11115 r270 top
J64 "TSW-102-07-G-S" TSW-102-07-G-S 999.68,8685.66 r0 top
J67 "TSW-102-07-G-S" TSW-102-07-G-S 777.68,8686.66 r0 top
J68 "TSW-102-07-G-S" TSW-102-07-G-S 1001.47,7263.53 r0 top
J71 "800-10-003-10-001000" Mill-Max_800-10-003-10-001000 5829,10045 r270 top
J72 "651305142821" 651305142821 6706.97,9538.59 r90 top
J73 "142-0771-831" JOHNSON_142-0771-831 0,7228.57 r90 top
J74 "142-0701-201" Johnson_142-0701-20x 2339.42,804.02 r90 top
J75 "800-10-003-10-001000" Mill-Max_800-10-003-10-001000 5956.31,5911.36 r270 top
J76 "142-0771-831" JOHNSON_142-0771-831 0,2860.42 r90 top
J77 "142-0771-831" JOHNSON_142-0771-831 0,2304.33 r90 top
J78 "TSW-102-07-G-S" TSW-102-07-G-S 779.47,7264.53 r0 top
J79 "TSW-102-07-G-S" TSW-102-07-G-S 1002.99,2339.29 r0 top
J80 "142-0771-831" JOHNSON_142-0771-831 0,1441.09 r90 top
J81 "142-0771-831" JOHNSON_142-0771-831 0,885 r90 top
J82 "TSW-102-07-G-S" TSW-102-07-G-S 780.99,2340.29 r0 top
J83 "TSW-102-07-G-S" TSW-102-07-G-S 1003.07,919.96 r0 top
J84 "TSW-102-07-G-S" TSW-102-07-G-S 781.07,920.96 r0 top
J85 "800-10-005-10-001000" Mill-Max_800-10-005-10-001000 5285,10663 r180 top
L1 "LQW18AN5N6D10D" LQW18A 1316.72,8990.13 r90 top
L2 "0603HC-3N9XJLU" 0603HC 1425.72,8986.13 r270 top
L3 "LQW18AN5N6D10D" LQW18A 1316.72,8885.13 r270 top
L4 "0603HC-3N9XJLU" 0603HC 1425.72,8884.13 r90 top
L5 "LQW18AN5N6D10D" LQW18A 1318.52,7568.01 r90 top
L6 "0603HC-3N9XJLU" 0603HC 1427.52,7564.01 r270 top
L7 "LQW18AN5N6D10D" LQW18A 1318.52,7463.01 r270 top
L8 "0603HC-3N9XJLU" 0603HC 1427.52,7462.01 r90 top
L9 "LQW18AN5N6D10D" LQW18A 1320.04,2643.77 r90 top
L10 "0603HC-3N9XJLU" 0603HC 1429.04,2639.77 r270 top
L11 "LQW18AN5N6D10D" LQW18A 1320.04,2538.77 r270 top
L12 "0603HC-3N9XJLU" 0603HC 1429.04,2537.77 r90 top
L13 "LQW18AN5N6D10D" LQW18A 1320.11,1224.44 r90 top
L14 "0603HC-3N9XJLU" 0603HC 1429.11,1220.44 r270 top
L15 "LQW18AN5N6D10D" LQW18A 1320.11,1119.44 r270 top
L16 "0603HC-3N9XJLU" 0603HC 1429.11,1118.44 r90 top
L17 "LQG15HS18NJ02D" IND_LQG15H 2216.07,6393.77 r270 top
L18 "LQG15HS18NJ02D" IND_LQG15H 2468.81,6256.72 r180 top
L19 "LQG15HS18NJ02D" IND_LQG15H 2335.55,3424.2 r90 top
L20 "LQG15HS18NJ02D" IND_LQG15H 2083.09,3561.55 r0 top
L21 "BLM18SG121TN1D" 0603 5512.38,5611.02 r90 bottom
L22 "BLM18AG121SN1D" 0603 4846.97,4761.02 r90 bottom
L23 "BLM18AG121SN1D" 0603 4350.97,4648.02 r90 top
L24 "BLM18AG121SN1D" 0603 4565.97,4652.02 r90 bottom
L25 "BLM18AG121SN1D" 0603 4627.97,4652.02 r90 bottom
L26 "BLM18AG121SN1D" 0603 4876.97,4904.02 r180 bottom
L27 "BLM18AG121SN1D" 0603 4876.97,4969.02 r180 bottom
L28 "BLM18AG121SN1D" 0603 4876.97,5031.02 r180 bottom
L29 "BLM18AG121SN1D" 0603 4908.97,5142.02 r270 bottom
L30 "BLM18AG121SN1D" 0603 4737.55,5168.44 r180 bottom
L31 "BLM18AG121SN1D" 0603 4365.97,5207.02 r270 top
L32 "BLM18SG260TN1D" 0603 5630.88,9695.97 r90 bottom
L33 "BLM18SG260TN1D" 0603 5662.88,9959.97 r180 bottom
L34 "BLM18SG260TN1D" 0603 5962,9460.18 r90 top
L35 "BLM41PG102SN1L" 1806_HIGHSPEED 2164.06,7870.63 r0 bottom
L36 "BLM41PG102SN1L" 1806_HIGHSPEED 2160,1520 r0 bottom
L37 "BLM41PG102SN1L" 1806_HIGHSPEED 2100.63,8620.28 r270 bottom
L38 "BLM41PG102SN1L" 1806_HIGHSPEED 2090,2270 r270 bottom
L39 "BLM41PG102SN1L" 1806_HIGHSPEED 2783.9,7151.69 r180 bottom
L40 "BLM41PG102SN1L" 1806_HIGHSPEED 2763.64,793.93 r180 bottom
L41 "BLM41PG102SN1L" 1806_HIGHSPEED 1650.17,5119.8 r90 top
L42 "BLM41PG102SN1L" 1806_HIGHSPEED 2910.8,6136.28 r90 top
L43 "BLM41PG102SN1L" 1806_HIGHSPEED 1431.34,4712.4 r270 top
L44 "BLM41PG102SN1L" 1806_HIGHSPEED 1401.43,4288.16 r0 top
L45 "BLM41PG102SN1L" 1806_HIGHSPEED 5297.23,3637.01 r90 top
L46 "BLM41PG102SN1L" 1806_HIGHSPEED 5977,5245 r90 top
L47 "BLM41PG102SN1L" 1806_HIGHSPEED 4649.85,10620.25 r270 top
L48 "BLM18SG121TN1D" 0603 1041.54,9419.71 r0 top
L49 "BLM18SG121TN1D" 0603 1044.44,3103.29 r0 top
L50 "BLM18SG121TN1D" 0603 1043.34,7997.59 r0 top
L51 "BLM18SG121TN1D" 0603 1043.51,1678.95 r0 top
L52 "BLM18SG121TN1D" 0603 844.91,9419.79 r180 top
L53 "BLM18SG121TN1D" 0603 847.81,3103.36 r180 top
L54 "BLM18SG121TN1D" 0603 846.71,7997.66 r180 top
L55 "BLM18SG121TN1D" 0603 846.88,1679.02 r180 top
L56 "BLM18SG121TN1D" 0603 5788.35,6058.72 r90 bottom
L57 "BLM41PG102SN1L" 1806_HighSpeed 2777,10272 r270 bottom
L58 "BLM41PG102SN1L" 1806_HighSpeed 2177,10272 r270 bottom
L59 "BLM41PG102SN1L" 1806_HighSpeed 3269,10272 r270 bottom
L60 "BLM18SG121TN1D" 0603 1073.29,8336.09 r180 bottom
L61 "BLM18SG121TN1D" 0603 538.91,8336.79 r0 bottom
L62 "BLM18SG121TN1D" 0603 1081.16,6914.29 r180 bottom
L63 "BLM18SG121TN1D" 0603 540.71,6914.66 r0 bottom
L64 "BLM18SG121TN1D" 0603 1096.86,2013.19 r180 bottom
L65 "BLM18SG121TN1D" 0603 541.81,2020.36 r0 bottom
L66 "BLM18SG121TN1D" 0603 1087.53,599.12 r180 bottom
L67 "BLM18SG121TN1D" 0603 540.88,596.02 r0 bottom
L68 "BLM41PG102SN1L" 1806_HighSpeed 1321,10272 r270 bottom
L69 "BLM41PG102SN1L" 1806_HighSpeed 1121,10272 r270 bottom
L70 "BLM41PG102SN1L" 1806_HighSpeed 621,10272 r270 bottom
L71 "BLM41PG102SN1L" 1806_HighSpeed 321,10272 r270 bottom
L72 "BLM41PG102SN1L" 1806_HIGHSPEED 6365,9178 r270 top
L73 "BLM41PG102SN1L" 1806_HIGHSPEED 2792,4563 r270 top
L74 "BLM41PG102SN1L" 1806_HighSpeed 3478,10272 r270 bottom
L75 "WE-LPF, 748112024" WE-LPF_0603 1621.75,9011 r90 top
L76 "WE-LPF, 748112024" WE-LPF_0603 1621.75,8859 r90 top
L77 "WE-LPF, 748112024" WE-LPF_0603 1621.75,7589.6 r90 top
L78 "WE-LPF, 748112024" WE-LPF_0603 1621.75,7437.4 r90 top
L79 "WE-LPF, 748112024" WE-LPF_0603 1621.75,2665.31 r90 top
L80 "WE-LPF, 748112024" WE-LPF_0603 1621.75,2513 r90 top
L81 "WE-LPF, 748112024" WE-LPF_0603 1621.75,1245.9 r90 top
L82 "WE-LPF, 748112024" WE-LPF_0603 1621.7,1093.8 r90 top
L83 "BLM41PG102SN1L" 1806_HighSpeed 2980.24,10272 r270 bottom
L84 "BLM41PG102SN1L" 1806_HighSpeed 2480.24,10272 r270 bottom
L85 "BLM41PG102SN1L" 1806_HighSpeed 1621,10270 r270 bottom
L86 "BLM41PG102SN1L" 1806_HighSpeed 823,10272 r270 bottom
L87 "BLM41PG102SN1L" 1806_HighSpeed 3186,11419 r0 bottom
L88 "BLM41PG102SN1L" 1806_HighSpeed 2322,11420 r0 bottom
L89 "BLM41PG102SN1L" 1806_HighSpeed 4036,11422.92 r0 bottom
L90 "BLM41PG102SN1L" 1806_HighSpeed 1616.05,11423.14 r0 bottom
L91 "BLM41PG102SN1L" 1806_HighSpeed 939,11423.92 r180 bottom
L92 "BLM41PG102SN1L" 1806_HighSpeed 4286,11266 r180 top
L93 "30Ω" "WE-CBF_1210_High Current" 2204.76,8726.19 r270 top
L94 "30Ω" "WE-CBF_1210_High Current" 2199,2376.87 r270 top
L95 "30Ω" "WE-CBF_1210_High Current" 2175,7821 r90 top
L96 "30Ω" "WE-CBF_1210_High Current" 2178,1463 r90 top
LBL1 "Size: 0.65\" x 0.20 \"" Label_650x200 5106,187 r180 top
LF1 "LFL182G45TC3B746" FIL_LFL18_TC1 1727.22,8993.95 r0 top
LF2 "LFL182G45TC3B746" FIL_LFL18_TC1 1727.32,8842.27 r0 top
LF3 "LFL182G45TC3B746" FIL_LFL18_TC1 1730.84,7571.87 r0 top
LF4 "LFL182G45TC3B746" FIL_LFL18_TC1 1730.84,7419.87 r0 top
LF5 "LFL182G45TC3B746" FIL_LFL18_TC1 1730.84,2648.27 r0 top
LF6 "LFL182G45TC3B746" FIL_LFL18_TC1 1730.84,2496.27 r0 top
LF7 "LFL182G45TC3B746" FIL_LFL18_TC1 1730.84,1229.17 r0 top
LF8 "LFL182G45TC3B746" FIL_LFL18_TC1 1730.84,1077.17 r0 top
Logo1 "ESD Susceptible" ESD_Overlay_Large 4969,2071 r0 top
Logo2 "Pb-Free Symbol" Pb-Free_Overlay_Small 560,4780 r0 top
Logo3 "FCC disclaimer" FCC_disclaimer 4085,798 r90 top
Logo4 "EU RoHS Exempt Logo" EURoHS_Exempt_60mil 7237,4939 r90 top
Logo5 "CAUTION.  READ USER GUIDE BEFORE USE" IEC_Caution_Medium 561,5153 r0 top
OSCinM1 "142-0701-201" JOHNSON_142-0701-20X 2536.66,5135.32 r90 top
OSCinM2 "142-0701-201" Johnson_142-0701-20x 2014.46,4682.16 r270 top
OSCinM3 "142-0701-201" Johnson_142-0701-20x 5262.06,6476.85 r0 top
OSCinP1 "142-0701-201" JOHNSON_142-0701-20X 2014.46,5135.82 r90 top
OSCinP2 "142-0701-201" Johnson_142-0701-20x 2537.16,4682.16 r270 top
OSCinP3 "142-0701-201" Johnson_142-0701-20x 5809.06,6476.85 r0 top
Q1 "MMBT3904" SOT-23 2734.1,9446.65 r180 top
Q2 "MMBT3904" SOT-23 2802.43,3100.88 r180 top
Q3 "CSD15571Q2" DQK0006C 5038.41,11442.42 r270 top
R1 "CRCW04022K00FKED" 0402#1 678.91,9210.99 r90 top
R2 "CRCW04020000Z0ED" 0402#1 738.91,9125.99 r0 top
R3 "CRCW04022K00FKED" 0402#1 628.91,9209.61 r270 top
R4 "CRCW04024R99FKED" 0402#1 1515.72,9011.13 r0 top
R5 "ERJ-2RKF1001X" 0402#1 508.91,8966.97 r0 bottom
R6 "CRCW0402127RFKED" 0402#1 508.91,8966.99 r0 top
R7 "CRCW04021K21FKED" 0402#1 1515.72,8961.13 r180 top
R8 "CRCW040222R6FKED" 0402#1 399.59,9052.69 r315 top
R9 "CRCW040215R0FKED" 0402#1 788.91,8960.99 r0 top
R10 "CRCW04020000Z0ED" 0402#1 894.09,8961.26 r180 top
R11 "CRCW04020000Z0ED" 0402#1 1189.09,8959.6 r180 top
R12 "CRCW040222R6FKED" 0402#1 398.91,8805.99 r45 top
R13 "CRCW040215R0FKED" 0402#1 788.91,8900.99 r0 top
R14 "CRCW04020000Z0ED" 0402#1 894.09,8901.26 r180 top
R15 "CRCW04020000Z0ED" 0402#1 1189.09,8909.6 r180 top
R16 "CRCW0402127RFKED" 0402#1 508.91,8895.01 r0 top
R17 "CRCW04021K21FKED" 0402#1 1515.72,8909.13 r180 top
R18 "CRCW04024R99FKED" 0402#1 1515.72,8859.13 r0 top
R19 "ERJ-2RKF1001X" 0402#1 508.91,8895.01 r180 bottom
R20 "CRCW0402365RFKED" 0402#1 328.91,8980.99 r315 top
R21 "CRCW0402365RFKED" 0402#1 328.91,8875.99 r45 top
R22 "CRCW040210K0FKED" 0402#1 1539.09,8701.26 r0 top
R23 "CRCW04020000Z0ED" 0402#1 1284.09,8701.26 r180 top
R24 "CRCW04020000Z0ED" 0402#1 1429.09,8596.26 r180 top
R25 "CRCW04022K00FKED" 0402#1 680.71,7788.86 r90 top
R26 "CRCW04020000Z0ED" 0402#1 740.71,7703.86 r0 top
R27 "CRCW04022K00FKED" 0402#1 630.71,7787.48 r270 top
R28 "CRCW04024R99FKED" 0402#1 1517.52,7589.01 r0 top
R29 "ERJ-2RKF1001X" 0402#1 510.71,7544.85 r0 bottom
R30 "CRCW0402127RFKED" 0402#1 510.71,7544.86 r0 top
R31 "CRCW04021K21FKED" 0402#1 1517.52,7539.01 r180 top
R32 "CRCW040222R6FKED" 0402#1 401.38,7630.57 r315 top
R33 "CRCW040215R0FKED" 0402#1 790.71,7538.86 r0 top
R34 "CRCW04020000Z0ED" 0402#1 895.89,7539.13 r180 top
R35 "CRCW04020000Z0ED" 0402#1 1190.89,7537.48 r180 top
R36 "CRCW040222R6FKED" 0402#1 400.71,7383.86 r45 top
R37 "CRCW040215R0FKED" 0402#1 790.71,7478.86 r0 top
R38 "CRCW04020000Z0ED" 0402#1 895.89,7479.13 r180 top
R39 "CRCW04020000Z0ED" 0402#1 1190.89,7487.48 r180 top
R40 "CRCW0402127RFKED" 0402#1 510.71,7472.88 r0 top
R41 "CRCW04021K21FKED" 0402#1 1517.52,7487.01 r180 top
R42 "CRCW04024R99FKED" 0402#2 1962.52,7437.01 r0 top
R43 "ERJ-2RKF1001X" 0402#1 510.71,7472.88 r180 bottom
R44 "CRCW0402365RFKED" 0402#1 330.71,7558.86 r315 top
R45 "CRCW0402365RFKED" 0402#1 330.71,7453.86 r45 top
R46 "CRCW040210K0FKED" 0402#1 1540.89,7279.13 r0 top
R47 "CRCW04020000Z0ED" 0402#1 1285.89,7279.13 r180 top
R48 "CRCW04020000Z0ED" 0402#1 1430.89,7174.13 r180 top
R49 "CRCW04028K06FKED" 0402#1 5286.21,7277.18 r0 top
R50 "CRCW04021K20JNED" 0402#1 4910.21,7409.18 r180 top
R51 "ERJ-2RKF1004X" 0402#1 4840.21,7154.18 r90 top
R52 "ERJ-2RKF1002X" 0402#1 3573.08,9271.88 r180 bottom
R53 "ERJ-2RKF1002X" 0402#1 3573.08,9172.88 r180 bottom
R54 "ERJ-2RKF1001X" 0402#1 3891.8,9271.99 r180 bottom
R55 "ERJ-2RKF1001X" 0402#1 3891.8,9171.99 r180 bottom
R56 "ERJ-2RKF1001X" 0402#1 3891.8,9071.99 r180 bottom
R57 "ERJ-2RKF1001X" 0402#1 3891.8,8970.99 r180 bottom
R58 "ERJ-2RKF1002X" 0402#1 3573.08,9071.88 r180 bottom
R59 "ERJ-2RKF1002X" 0402#1 3573.08,8971.88 r180 bottom
R60 "CRCW04021K33FKED" 0402#1 5286.21,7228.18 r180 top
R61 "CRCW04021K20JNED" 0402#1 5314.21,7394.18 r180 top
R62 "ERJ-2RKF1004X" 0402#1 5308.21,7102.18 r90 top
R63 "ERJ-2RKF1001X" 0402#1 3080.3,9260.91 r0 bottom
R64 "ERJ-2RKF1001X" 0402#1 3217.3,9260.91 r180 bottom
R65 "ERJ-2RKF1002X" 0402#1 3081.3,8991.91 r180 bottom
R66 "ERJ-2RKF1002X" 0402#1 3214.3,8991.91 r0 bottom
R67 "CRCW04020000Z0ED" 0402#1 1994.48,8502.3 r0 top
R68 "CRCW04020000Z0ED" 0402#1 2018.1,8478.68 r90 top
R69 "CRCW04020000Z0ED" 0402#1 2018.1,8372.92 r270 top
R70 "CRCW04020000Z0ED" 0402#1 1994.48,8349.3 r0 top
R71 "ERJ-2RKF1001X" 0402#1 2116.17,8376.09 r90 bottom
R72 "CRCW04022K10FKED" 0402#1 2166.17,8376.09 r270 bottom
R73 "CRCW0402100RFKED" 0402#1 1906.17,8223.5 r90 top
R74 "ERJ-2RKF1002X" 0402#1 3215.1,9447.03 r0 top
R75 "ERJ-2RKF1002X" 0402#1 3215.1,9510.03 r0 top
R76 "ERJ-2RKF1002X" 0402#1 3089.1,9623.03 r180 top
R77 "CRCW0603750RJNEA" 0603 3191.1,9349.03 r270 top
R78 "CRCW04020000Z0ED" 0402#1 2603.93,9568.94 r90 bottom
R79 "CRCW04020000Z0ED" 0402#1 2360.16,9568.55 r90 bottom
R80 "RC0603JR-071K3L" 0603 3219.1,9567.03 r0 top
R81 "RC0603JR-071K3L" 0603 3219.1,9630.03 r0 top
R82 "CRCW04022K00FKED" 0402#1 682.23,2864.63 r90 top
R83 "CRCW04020000Z0ED" 0402#1 742.23,2779.63 r0 top
R84 "CRCW04022K00FKED" 0402#1 632.23,2863.25 r270 top
R85 "CRCW04024R99FKED" 0402#1 1519.04,2664.77 r0 top
R86 "ERJ-2RKF1001X" 0402#1 512.23,2620.61 r0 bottom
R87 "CRCW0402127RFKED" 0402#1 512.23,2620.63 r0 top
R88 "CRCW04021K21FKED" 0402#1 1519.04,2614.77 r180 top
R89 "CRCW040222R6FKED" 0402#1 402.9,2706.33 r315 top
R90 "CRCW040215R0FKED" 0402#1 792.23,2614.63 r0 top
R91 "CRCW04020000Z0ED" 0402#1 897.41,2614.9 r180 top
R92 "CRCW04020000Z0ED" 0402#1 1192.41,2613.24 r180 top
R93 "CRCW040222R6FKED" 0402#1 402.23,2459.63 r45 top
R94 "CRCW040215R0FKED" 0402#1 792.23,2554.63 r0 top
R95 "CRCW04020000Z0ED" 0402#1 897.41,2554.9 r180 top
R96 "CRCW04020000Z0ED" 0402#1 1192.41,2563.24 r180 top
R97 "CRCW0402127RFKED" 0402#1 512.23,2548.64 r0 top
R98 "CRCW04021K21FKED" 0402#1 1519.04,2562.77 r180 top
R99 "CRCW04024R99FKED" 0402#1 1519.04,2512.77 r0 top
R100 "ERJ-2RKF1001X" 0402#1 512.23,2548.64 r180 bottom
R101 "CRCW0402365RFKED" 0402#1 332.23,2634.63 r315 top
R102 "CRCW0402365RFKED" 0402#1 332.23,2529.63 r45 top
R103 "CRCW040210K0FKED" 0402#1 1542.41,2354.9 r0 top
R104 "CRCW04020000Z0ED" 0402#1 1287.41,2354.9 r180 top
R105 "CRCW04020000Z0ED" 0402#1 1432.41,2249.9 r180 top
R106 "CRCW04022K00FKED" 0402#1 682.3,1445.29 r90 top
R107 "CRCW04020000Z0ED" 0402#1 742.3,1360.29 r0 top
R108 "CRCW04022K00FKED" 0402#1 632.3,1443.91 r270 top
R109 "CRCW04024R99FKED" 0402#1 1519.11,1245.44 r0 top
R110 "ERJ-2RKF1001X" 0402#1 512.3,1201.28 r0 bottom
R111 "CRCW0402127RFKED" 0402#1 512.3,1201.29 r0 top
R112 "CRCW04021K21FKED" 0402#1 1519.11,1195.44 r180 top
R113 "CRCW040222R6FKED" 0402#1 402.98,1287 r315 top
R114 "CRCW040215R0FKED" 0402#1 792.3,1195.29 r0 top
R115 "CRCW04020000Z0ED" 0402#1 897.48,1195.56 r180 top
R116 "CRCW04020000Z0ED" 0402#1 1192.48,1193.91 r180 top
R117 "CRCW040222R6FKED" 0402#1 402.3,1040.29 r45 top
R118 "CRCW040215R0FKED" 0402#1 792.3,1135.29 r0 top
R119 "CRCW04020000Z0ED" 0402#1 897.48,1135.56 r180 top
R120 "CRCW04020000Z0ED" 0402#1 1192.48,1143.91 r180 top
R121 "CRCW0402127RFKED" 0402#1 512.3,1129.31 r0 top
R122 "CRCW04021K21FKED" 0402#1 1519.11,1143.44 r180 top
R123 "CRCW04024R99FKED" 0402#1 1519.11,1093.44 r0 top
R124 "ERJ-2RKF1001X" 0402#1 512.3,1129.31 r180 bottom
R125 "CRCW0402365RFKED" 0402#1 332.3,1215.29 r315 top
R126 "CRCW0402365RFKED" 0402#1 332.3,1110.29 r45 top
R127 "CRCW040210K0FKED" 0402#1 1542.48,935.56 r0 top
R128 "CRCW04020000Z0ED" 0402#1 1287.48,935.56 r180 top
R129 "CRCW04020000Z0ED" 0402#1 1432.48,830.56 r180 top
R130 "CRCW04028K06FKED" 0402#1 5369.3,869.25 r0 top
R131 "CRCW04021K20JNED" 0402#1 4993.3,1001.25 r180 top
R132 "ERJ-2RKF1004X" 0402#1 4923.3,746.25 r90 top
R133 "ERJ-2RKF1002X" 0402#1 3654.72,2986.99 r180 bottom
R134 "ERJ-2RKF1002X" 0402#1 3654.72,2887.99 r180 bottom
R135 "ERJ-2RKF1001X" 0402#1 3968.72,2986.99 r180 bottom
R136 "ERJ-2RKF1001X" 0402#1 3968.72,2886.99 r180 bottom
R137 "ERJ-2RKF1001X" 0402#1 3968.72,2786.99 r180 bottom
R138 "ERJ-2RKF1001X" 0402#1 3968.72,2685.99 r180 bottom
R139 "ERJ-2RKF1002X" 0402#1 3654.72,2786.99 r180 bottom
R140 "ERJ-2RKF1002X" 0402#1 3654.72,2686.99 r180 bottom
R141 "CRCW04021K33FKED" 0402#1 5369.3,820.25 r180 top
R142 "CRCW04021K20JNED" 0402#1 5397.3,986.25 r180 top
R143 "ERJ-2RKF1004X" 0402#1 5391.3,694.25 r90 top
R144 "ERJ-2RKF1001X" 0402#1 3149.99,2905.76 r0 bottom
R145 "ERJ-2RKF1001X" 0402#1 3280.28,2906.49 r180 bottom
R146 "ERJ-2RKF1002X" 0402#1 3150.28,2645.49 r180 bottom
R147 "ERJ-2RKF1002X" 0402#1 3268.28,2645.49 r0 bottom
R148 "CRCW04020000Z0ED" 0402#1 1987.5,2155.51 r0 top
R149 "CRCW04020000Z0ED" 0402#1 2011.12,2131.88 r90 top
R150 "CRCW04020000Z0ED" 0402#1 2011.12,2026.13 r270 top
R151 "CRCW04020000Z0ED" 0402#1 1987.5,2002.51 r0 top
R152 "ERJ-2RKF1001X" 0402#1 2109.5,2032.1 r90 bottom
R153 "CRCW04022K10FKED" 0402#1 2159.5,2032.1 r270 bottom
R154 "CRCW0402100RFKED" 0402#1 1909.5,1876.1 r90 top
R155 "ERJ-2RKF1002X" 0402#1 3283.43,3101.26 r0 top
R156 "ERJ-2RKF1002X" 0402#1 3283.43,3164.26 r0 top
R157 "ERJ-2RKF1002X" 0402#1 3157.43,3277.26 r180 top
R158 "CRCW0603750RJNEA" 0603 3259.43,3003.26 r270 top
R159 "CRCW04020000Z0ED" 0402#1 2669.26,3222.95 r90 bottom
R160 "CRCW04020000Z0ED" 0402#1 2425.49,3222.55 r90 bottom
R161 "RC0603JR-071K3L" 0603 3287.43,3221.26 r0 top
R162 "RC0603JR-071K3L" 0603 3287.43,3284.26 r0 top
R163 "CRCW04021K50JNED" 0402#1 5872.89,6034.98 r90 top
R164 "FC0402E50R0BST1" 0402L 2236.04,6343.87 r180 top
R165 "CRCW06030000Z0EA" 0603 2245.1,5836.81 r90 bottom
R166 "CRCW04021K50JNED" 0402#1 5872.89,5787.73 r90 top
R167 "CRCW06030000Z0EA" 0603L 2436.28,6033.92 r180 bottom
R168 "FC0402E50R0BST1" 0402L 2311.5,6343.55 r0 top
R169 "CRCW06030000Z0EA" 0603L 2362.81,6338.72 r180 bottom
R170 "CRCW06030000Z0EA" 0603L 2404.81,6165.72 r270 bottom
R171 "CRCW06030000Z0EA" 0603 2069.93,6477.29 r180 top
R172 "CRCW0603100KJNEA" 0603 2108.66,5888.82 r90 top
R173 "CRCW06030000Z0EA" 0603 1938.66,5991.92 r180 top
R174 "CRCW04020000Z0ED" 0402_FILTER 1727.22,9010.68 r0 top
R175 "FC0402E50R0BST1" 0402L 2418.59,6161.28 r90 top
R176 "CRCW060356R0JNEA" 0603 2463.66,5788.82 r315 top
R177 "CRCW06030000Z0EA" 0603 2509.66,5835.72 r315 top
R178 "CRCW04020000Z0ED" 0402#1 2105.31,6004.52 r180 bottom
R179 "RC0603JR-07270RL" 0603 2648.28,5788.92 r315 top
R180 "FC0402E50R0BST1" 0402L 2418.91,6236.74 r90 top
R181 "CRCW04020000Z0ED" 0402_FILTER 1727.22,8858.68 r0 top
R182 "CRCW040210K0DHEDP" 0402#1 2105.31,5955.52 r180 bottom
R183 "CRCW040210K0DHEDP" 0402#1 2072.31,6308.52 r180 bottom
R184 "CRCW04020000Z0ED" 0402#1 2096.31,6220.52 r270 bottom
R185 "CRCW04020000Z0ED" 0402#1 2252.86,5453.63 r270 top
R186 "CRCW04020000Z0ED" 0402_FILTER 1730.84,7588.6 r0 top
R187 "CRCW0603100RFKEA" 0603 2435.81,6503.72 r90 top
R188 "CRCW04020000Z0ED" 0402_FILTER 1730.84,7436.6 r0 top
R189 "CRCW060351R0JNEA" 0603 1983.66,5542.82 r180 top
R190 "RC0603JR-07330RL" 0603 2467.81,6406.72 r180 top
R191 "CRCW06030000Z0EA" 0603 2014.46,5445.82 r90 top
R192 "CRCW06030000Z0EA" 0603 2092.26,5616.42 r45 top
R193 "CRCW04020000Z0ED" 0402#1 1532.81,5730.14 r270 bottom
R194 "CRCW0402100RJNED" 0402#1 1559.66,5559.32 r180 bottom
R195 "CRCW04020000Z0ED" 0402#1 1984.54,8292.24 r180 top
R196 "CRCW0603100RFKEA" 0603L 2273.66,5788.82 r180 top
R197 "CRCW04020000Z0ED" 0402#1 1984.54,8157.76 r180 top
R198 "CRCW06030000Z0EA" 0603 2537.16,5445.82 r90 top
R199 "CRCW06030000Z0EA" 0603 2459.26,5617.42 r315 top
R200 "CRCW04020000Z0ED" 0402#1 1482.81,5730.52 r90 bottom
R201 "CRCW0402100RJNED" 0402#1 1459.66,5559.32 r180 bottom
R202 "CRCW060351R0JNEA" 0603 2568.66,5542.82 r180 top
R203 "CRCW04020000Z0ED" 0402#1 2301.86,5453.63 r90 top
R204 "CRCW04020000Z0ED" 0402_FILTER 1730.84,2665 r0 top
R205 "FC0402E50R0BST1" 0402L 2315.57,3474.1 r0 top
R206 "CRCW06030000Z0EA" 0603 2306.51,3981.17 r270 bottom
R207 "CRCW04020000Z0ED" 0402_FILTER 1730.84,2513 r0 top
R208 "CRCW06030000Z0EA" 0603L 2115.34,3784.06 r0 bottom
R209 "FC0402E50R0BST1" 0402L 2240.11,3474.42 r180 top
R210 "CRCW06030000Z0EA" 0603L 2183.88,3477.61 r0 bottom
R211 "CRCW06030000Z0EA" 0603L 2142.48,3650.01 r90 bottom
R212 "CRCW06030000Z0EA" 0603 2482.39,3339.98 r0 top
R213 "CRCW0603100KJNEA" 0603 2442.96,3929.16 r270 top
R214 "CRCW06030000Z0EA" 0603 2612.96,3826.06 r0 top
R215 "CRCW04020000Z0ED" 0402_FILTER 1730.84,1245.9 r0 top
R216 "FC0402E50R0BST1" 0402L 2133.02,3656.69 r270 top
R217 "CRCW06030000Z0EA" 0603 2041.96,3983.16 r135 top
R218 "CRCW060356R0JNEA" 0603 2086.6,4027.8 r135 top
R219 "CRCW04020000Z0ED" 0402#1 2446.3,3813.45 r0 bottom
R220 "RC0603JR-07270RL" 0603 1903.34,4029.06 r135 top
R221 "FC0402E50R0BST1" 0402L 2132.7,3581.23 r270 top
R222 "CRCW04020000Z0ED" 0402_FILTER 1730.84,1093.9 r0 top
R223 "CRCW040210K0DHEDP" 0402#1 2446.3,3862.45 r0 bottom
R224 "CRCW040210K0DHEDP" 0402#1 2479.3,3509.45 r0 bottom
R225 "CRCW04020000Z0ED" 0402#1 2455.3,3597.45 r90 bottom
R226 "CRCW04020000Z0ED" 0402#1 2299.16,4363.73 r90 top
R227 "CRCW0603100RFKEA" 0603 2115.3,3314.76 r270 top
R228 "ERJ-2RKF1002X" 0402#1 4345.89,5057 r0 bottom
R229 "CRCW04020000Z0ED" 0402#1 5679,3451 r270 bottom
R230 "CRCW060351R0JNEA" 0603 2567.96,4275.16 r0 top
R231 "RC0603JR-07330RL" 0603 2083.8,3411.26 r0 top
R232 "CRCW06030000Z0EA" 0603 2537.16,4372.16 r270 top
R233 "CRCW06030000Z0EA" 0603 2459.36,4201.56 r225 top
R234 "CRCW04020000Z0ED" 0402#1 3018.8,4087.83 r90 bottom
R235 "CRCW0402100RJNED" 0402#1 2992.46,4261.16 r0 bottom
R236 "CRCW04020000Z0ED" 0402#1 1987.88,1944.84 r180 top
R237 "CRCW0603100RFKEA" 0603L 2277.96,4029.16 r0 top
R238 "CRCW04020000Z0ED" 0402#1 1987.88,1810.35 r180 top
R239 "CRCW04020000Z0ED" 0402#1 3067.83,4087.94 r270 bottom
R240 "CRCW0402100RJNED" 0402#1 3091.46,4261.16 r0 bottom
R241 "CRCW06030000Z0EA" 0603 2014.46,4372.16 r270 top
R242 "CRCW06030000Z0EA" 0603 2092.36,4204.05 r135 top
R243 "CRCW060351R0JNEA" 0603 1982.96,4275.16 r0 top
R244 "CRCW04020000Z0ED" 0402#1 2248.66,4364.22 r270 top
R245 "CRCW04020000Z0ED" 0402#1 3164.5,5107.79 r90 top
R246 "CRCW04020000Z0ED" 0402#1 3103.5,4965.79 r180 top
R247 "CRCW04020000Z0ED" 0402#1 3521.5,4966.29 r0 top
R248 "CRCW04020000Z0ED" 0402#1 3521.5,5021.29 r0 top
R249 "CRCW04020000Z0ED" 0402#1 3279.5,5176.79 r90 top
R250 "CRCW04020000Z0ED" 0402#1 3330.5,5177.29 r90 top
R251 "CRCW04020000Z0ED" 0402#1 3270.5,4785.29 r270 top
R252 "CRCW04020000Z0ED" 0402#1 2982,5120.29 r90 top
R253 "CRCW04020000Z0ED" 0402#1 3335.5,4582.04 r90 bottom
R254 "CRCW04020000Z0ED" 0402#1 3007,5091.58 r180 top
R255 "CRCW04020000Z0ED" 0402#3 3105,5039.58 r180 top
R256 "CRCW04020000Z0ED" 0402#1 2981,5018.29 r270 top
R257 "CRCW04020000Z0ED" 0402#1 3384.5,4582.04 r90 bottom
R258 "CRCW0402160RJNED" 0402#1 2929.5,5015.79 r90 top
R259 "CRCW0402160RJNED" 0402#1 2929.5,5119.79 r270 top
R260 "CRCW04020000Z0ED" 0402#1 2981,4914.29 r90 top
R261 "CRCW04020000Z0ED" 0402#1 3335.75,4523.54 r90 top
R262 "CRCW04020000Z0ED" 0402#1 3007,4889.29 r180 top
R263 "CRCW04020000Z0ED" 0402#1 3335.5,4629.29 r90 top
R264 "CRCW04020000Z0ED" 0402#1 3007,4840.29 r180 top
R265 "CRCW04020000Z0ED" 0402#1 2980,4813.29 r270 top
R266 "CRCW04020000Z0ED" 0402#1 3385.75,4523.54 r90 top
R267 "CRCW0402100RFKED" 0402#1 3359.5,4707.29 r180 top
R268 "CRCW0402160RJNED" 0402#1 2929,4813.29 r90 top
R269 "CRCW0402160RJNED" 0402#1 2929,4918.29 r270 top
R270 "CRCW04020000Z0ED" 0402#1 3384.5,4629.29 r90 top
R271 "CRCW04020000Z0ED" 0402#1 3917.47,5219.44 r180 top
